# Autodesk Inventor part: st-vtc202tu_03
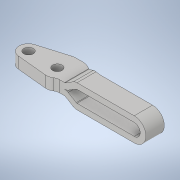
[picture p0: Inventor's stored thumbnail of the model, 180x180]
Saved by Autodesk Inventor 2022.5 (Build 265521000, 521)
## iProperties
Created: 2021-08
Part Number: st-vtc202tu_03
Material: 一般
Document SubType Name: Modeling
Designer: ImaoCorp
Density: 1 g/cm^3
Appearance: 既定
Author: ImaoCorp
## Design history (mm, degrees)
feature "st-vtc202tu_03"
node "ソリッド1"
